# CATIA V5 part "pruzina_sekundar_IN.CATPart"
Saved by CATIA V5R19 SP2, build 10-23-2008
Part number: Pruzina_sekundar_IN
Bounding box of the stored display mesh (mm): x -130.499 to 130.5, y -130.5 to 130.492, z 50 to 380
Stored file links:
  C:\Users\Martiin\Desktop\9.semestr\Projekt-diplomka\3D model\pruzina_sekundar_IN.CATPart
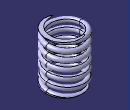
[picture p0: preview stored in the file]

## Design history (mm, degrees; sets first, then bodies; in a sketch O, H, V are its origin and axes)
Body1 (main body)
  Line1: type PtDir, RefPoint {point type Coord, X 0, Y 0, Z 0}, Direction xy-plane, Support zx-plane, Start 0, End 176
  Point1: type OnPlane, Support xy-plane, H 115, V 0, Direction (1, 0, 0)
  Helix1: Direction Line1, RefPoint Point1, Pitch 54.2857, Height 500, TaperAngle 0
  Plane1: type Normal, Curve Helix1, RefPoint Point1
  Sketch1 on Plane1, origin (0, 0, 0), H (-1, 0, 0), V (0, -0.0749, -0.9972)
    circle A1 centre (-115, 0) radius 15.5
    point P1 (-115, 0)
    reference projected point E1 (-115, 0) from Point1
    radius A1 = 15.5
    coincidence: E1 P1
  Rib1: profile Sketch1, centre curve Helix1
  Plane2: type Offset, RefPlane xy-plane, Offset 50
  Split1: SplitPlane Plane2
  Plane3: type Offset, RefPlane xy-plane, Offset 380
  Split2: SplitPlane Plane3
